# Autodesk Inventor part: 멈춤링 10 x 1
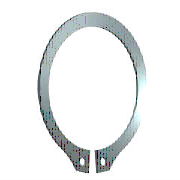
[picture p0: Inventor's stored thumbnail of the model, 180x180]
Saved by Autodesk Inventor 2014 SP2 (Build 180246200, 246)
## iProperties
IsCustomPart: 0
Created: 2015-11
Part Number: 멈춤링 10 x 1
Material: 스테인리스강
Description: 리테이닝 링(C형)
Document SubType Name: Modeling
Standard: KS B 1336
Designer: mdu
Standards Organization: KS
Language: ko-KR
Size Designation: 10 x 1
Categories: <MemberInstance><Categories><Category DisplayName="샤프트 부품" InternalName="7f7aeb1f-a693-4053-b835-cee3144e0d98" Mnemonic="SHFT"><Category DisplayName="써클립" Inter
Density: 8.08 g/cm^3
Appearance: 반광택
Mass: 0.434929 g
Surface Area: 1.9243 cm^2
Volume: 0.0538279 cm^3
Author: mdu
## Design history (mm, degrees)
sketch "스케치1"
  geometry: L1 (-6, 0)-(6, 0) reference; L2 (0, 20.189)-(0, -80.536) reference; L3 (-48.09, 0)-(48.09, 0) reference; L4 (-0.3, -9.791)-(-0.3, -12.791); L5 (-0.3, -6.54)-(-0.3, -13.29); L6 (-2.795, 1.6)-(3.672, 1.6); L7 (0.3, -6.54)-(0.3, -13.29); L8 (0.3, -9.791)-(0.3, -12.791); C1 r 0.6 at (-1.2, -11.486); C2 r 0.6 at (1.2, -11.486); A1 r 4.8 centre (0, -5) between (0.3, -9.791) and (-0.3, -9.791); A2 r 6.2 centre (0, -4.6) between (2.988, -10.033) and (-2.988, -10.033); A3 r 7.796 centre (0, -5) between (-1.418, -12.666) and (-0.3, -12.791); A4 r 1.2 centre (-1.2, -11.486) between (-2.383, -11.285) and (-1.418, -12.666); A5 r 1.2 centre (-3.566, -11.084) between (-2.383, -11.285) and (-2.988, -10.033); A6 r 1.2 centre (3.566, -11.084) between (2.988, -10.033) and (2.383, -11.285); A7 r 1.2 centre (1.2, -11.486) between (1.418, -12.666) and (2.383, -11.285); A8 r 7.796 centre (0, -5) between (0.3, -12.791) and (1.418, -12.666)
  constraints: 16 point on circle, 12 end point, 10 centre point, 9 symmetric about line, 5 point on line, 4 tangent, 3 coincident, 2 horizontal, 1 perpendicular, 1 vertical, 5 other
  dimensions: "d0" = 9.6 diameter of A1 (= ND); "d1" = 3 distance of L4.end L4.start (= SRB2); "d6" = 0.3 distance between parallel lines of L2 L5 (= 0.25 x SD5); "d7" = 1.6 distance between parallel lines of L6 L3 (= SRB1); "d8" = 0.4 distance of A1.centre A2.centre (= 0.25 x SRB1); "d9" = 1.2 radius of A4 (= SD5); "d10" = 1.2 radius of A5 (= SD5); "d11" = 0.9 distance from line of L4 A4.centre (= 0.75 x SD5); "d12" = 1.2 diameter of C1 (= SD5); "d13" = 1.2 diameter of C2 (= SD5); "d14" = 5 distance from line of A1.centre L1 (= 0.5 x WD)
extrude "본체" new body sketch "스케치1" distance "d2" = 1 (= SD); taper "d3" = 0 deg
workaxis "Work Axis1"
workplane "Work Plane1"
body "Solid1"
other parameters: "SD" = 1 [user parameter; used in 1 equation term], "SRB1" = 1.6 [user parameter; used in 2 equation terms], "ND" = 9.6 [user parameter; used in 1 equation term], "SRB2" = 3 [user parameter; used in 1 equation term], "SD5" = 1.2 [user parameter; used in 6 equation terms], "d15" = 0, "d16" = 0, "d17" = 0, "d41" = 0, "d42" = 0, "SD3" = 9.3 [user parameter], "WDMAX" = 11 [user parameter]
